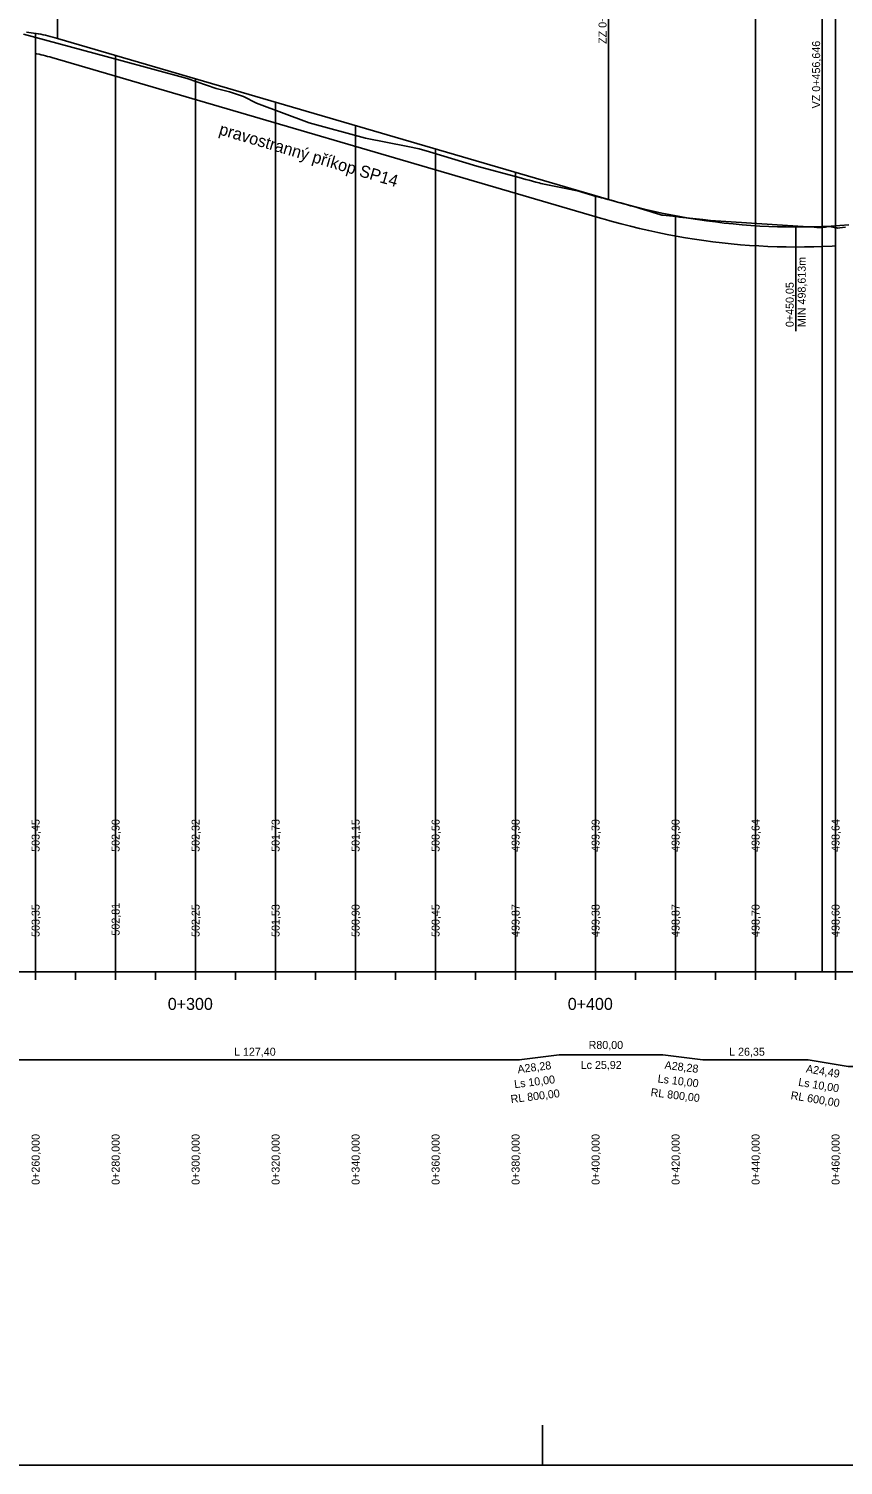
# Model space of a CAD drawing. Extents: x -632716 to -629545, y -1094726 to -1088285.
# Drawn here: x -632193.7 to -631990, y -1090378.9 to -1090019.9 of the extents above; entities that cross this region are included whole.
import ezdxf

# ---------------------------------------------------------------- set-up
doc = ezdxf.new("R2010")
doc.units = 0
for name, color, linetype in [('20', 7, 'Continuous'), ('Default', 7, 'Continuous'), ('formát', 7, 'Continuous'), ('NIVELETA_VYSKY', 7, 'Continuous'), ('PŘÍKOP', 7, 'Continuous'), ('REZ_POPIS', 7, 'Continuous'), ('REZ_TABULKA', 7, 'Continuous'), ('REZ_TENKA', 7, 'Continuous'), ('REZ_TLUSTA', 7, 'Continuous'), ('SKLONY_NIVELETA', 7, 'Continuous'), ('SKLONY_POPIS', 7, 'Continuous'), ('TECNY_NIVELETA', 7, 'Continuous'), ('TEREN_VYSKY', 7, 'Continuous'), ('VOZOVKA', 7, 'Continuous')]:
    doc.layers.add(name, color=color, linetype=linetype)

msp = doc.modelspace()

# ---------------------------------------------------------------- linework, layer by layer
at = {"layer": '20'}
for points in [[(-632191.95, -1090021.1), (-632191.95, -1090205.62), (-632191.95, -1090255.62), (-632191.95, -1090195.62)], [(-632171.95, -1090026.6), (-632171.95, -1090205.62), (-632171.95, -1090255.62), (-632171.95, -1090195.62)], [(-632151.95, -1090032.45), (-632151.95, -1090205.62), (-632151.95, -1090255.62), (-632151.95, -1090195.62)], [(-632131.95, -1090038.3), (-632131.95, -1090205.62), (-632131.95, -1090255.62), (-632131.95, -1090195.62)], [(-632111.95, -1090044.15), (-632111.95, -1090205.62), (-632111.95, -1090255.62), (-632111.95, -1090195.62)], [(-632091.95, -1090050), (-632091.95, -1090205.62), (-632091.95, -1090255.62), (-632091.95, -1090195.62)], [(-632071.95, -1090055.84), (-632071.95, -1090205.62), (-632071.95, -1090255.62), (-632071.95, -1090195.62)], [(-632051.95, -1090061.69), (-632051.95, -1090205.62), (-632051.95, -1090255.62), (-632051.95, -1090195.62)], [(-632031.95, -1090066.67), (-632031.95, -1090205.62), (-632031.95, -1090255.62), (-632031.95, -1090195.62)], [(-632011.95, -1090069.17), (-632011.95, -1090205.62), (-632011.95, -1090255.62), (-632011.95, -1090195.62)], [(-631991.95, -1090069.18), (-631991.95, -1090205.62), (-631991.95, -1090255.62), (-631991.95, -1090195.62)]]:
    msp.add_lwpolyline(points, dxfattribs=at)
at = {"layer": 'Default'}
msp.add_line((-632186.49, -1090022.35), (-632048.71, -1090062.64), dxfattribs=at)
for points in [[(-632194.25, -1090020.78), (-632193.65, -1090020.85), (-632193.06, -1090020.93), (-632192.46, -1090021.02), (-632191.86, -1090021.11), (-632191.27, -1090021.22), (-632190.67, -1090021.33), (-632190.07, -1090021.45), (-632189.48, -1090021.58), (-632188.88, -1090021.72), (-632188.28, -1090021.86), (-632187.68, -1090022.01), (-632187.09, -1090022.18), (-632186.49, -1090022.35)], [(-632048.71, -1090062.64), (-632046.48, -1090063.28), (-632044.26, -1090063.88), (-632042.03, -1090064.46), (-632039.81, -1090065), (-632037.58, -1090065.51), (-632035.36, -1090065.99), (-632033.13, -1090066.44), (-632030.91, -1090066.86), (-632028.68, -1090067.25), (-632026.46, -1090067.6), (-632024.23, -1090067.93), (-632022.01, -1090068.22), (-632019.78, -1090068.49), (-632017.56, -1090068.72), (-632015.33, -1090068.92), (-632013.11, -1090069.1), (-632010.88, -1090069.24), (-632008.66, -1090069.34), (-632006.43, -1090069.42), (-632004.21, -1090069.47), (-632001.98, -1090069.49), (-631999.76, -1090069.47), (-631997.53, -1090069.43), (-631993.08, -1090069.24), (-631990.86, -1090069.11), (-631988.63, -1090068.94)]]:
    msp.add_lwpolyline(points, dxfattribs=at)
at = {"layer": 'formát'}
msp.add_line((-632065.24, -1090378.9), (-632065.24, -1090368.9), dxfattribs=at)
msp.add_lwpolyline([(-632546.83, -1090378.9), (-629545.24, -1090378.9), (-629545.24, -1089784.9), (-632546.83, -1089784.9)], close=True, dxfattribs=at)
at = {"layer": 'PŘÍKOP'}
msp.add_line((-632187.89, -1090027.15), (-632050.11, -1090067.44), dxfattribs=at)
for points in [[(-632191.95, -1090026.18), (-632191.62, -1090026.24), (-632191.09, -1090026.34), (-632190.56, -1090026.46), (-632190.03, -1090026.58), (-632189.5, -1090026.71), (-632188.96, -1090026.85), (-632188.43, -1090026.99), (-632187.86, -1090027.15)], [(-632050.08, -1090067.45), (-632047.82, -1090068.1), (-632045.54, -1090068.72), (-632043.25, -1090069.31), (-632040.96, -1090069.86), (-632038.67, -1090070.39), (-632036.38, -1090070.89), (-632034.09, -1090071.35), (-632031.8, -1090071.78), (-632029.51, -1090072.18), (-632027.22, -1090072.55), (-632024.92, -1090072.88), (-632022.63, -1090073.19), (-632020.34, -1090073.46), (-632018.04, -1090073.7), (-632015.75, -1090073.91), (-632013.46, -1090074.08), (-632011.16, -1090074.23), (-632008.87, -1090074.34), (-632006.57, -1090074.42), (-632004.28, -1090074.47), (-632001.99, -1090074.49), (-631999.69, -1090074.47), (-631997.38, -1090074.43), (-631992.82, -1090074.24), (-631991.95, -1090074.18)]]:
    msp.add_lwpolyline(points, dxfattribs=at)
at = {"layer": 'REZ_TABULKA'}
msp.add_lwpolyline([(-632198.42, -1090277.62), (-632071.02, -1090277.62), (-632071.02, -1090277.62), (-632061.02, -1090276.37), (-632061.02, -1090276.37), (-632035.1, -1090276.37), (-632035.1, -1090276.37), (-632025.1, -1090277.62), (-632025.1, -1090277.62), (-631998.76, -1090277.62), (-631998.76, -1090277.62), (-631988.76, -1090279.29), (-631988.76, -1090279.29), (-631977.84, -1090279.29), (-631977.84, -1090279.29), (-631967.84, -1090277.62), (-631967.84, -1090277.62), (-631872.85, -1090277.62), (-631872.85, -1090277.22), (-631839.21, -1090277.22), (-631839.21, -1090277.62), (-631794.79, -1090277.62)], dxfattribs=at)
at = {"layer": 'REZ_TENKA'}
for p, q in [((-632191.95, -1090257.62), (-632191.95, -1090255.62)), ((-632181.95, -1090257.62), (-632181.95, -1090255.62)), ((-632171.95, -1090257.62), (-632171.95, -1090255.62)), ((-632161.95, -1090257.62), (-632161.95, -1090255.62)), ((-632141.95, -1090257.62), (-632141.95, -1090255.62)), ((-632131.95, -1090257.62), (-632131.95, -1090255.62)), ((-632121.95, -1090257.62), (-632121.95, -1090255.62)), ((-632111.95, -1090257.62), (-632111.95, -1090255.62)), ((-632101.95, -1090257.62), (-632101.95, -1090255.62)), ((-632091.95, -1090257.62), (-632091.95, -1090255.62)), ((-632081.95, -1090257.62), (-632081.95, -1090255.62)), ((-632071.95, -1090257.62), (-632071.95, -1090255.62)), ((-632061.95, -1090257.62), (-632061.95, -1090255.62)), ((-632041.95, -1090257.62), (-632041.95, -1090255.62)), ((-632031.95, -1090257.62), (-632031.95, -1090255.62)), ((-632021.95, -1090257.62), (-632021.95, -1090255.62)), ((-632011.95, -1090257.62), (-632011.95, -1090255.62)), ((-632001.95, -1090257.62), (-632001.95, -1090255.62)), ((-631991.95, -1090257.62), (-631991.95, -1090255.62))]:
    msp.add_line(p, q, dxfattribs=at)
at = {"layer": 'REZ_TLUSTA'}
for p, q in [((-632151.95, -1090257.62), (-632151.95, -1090253.62)), ((-632051.95, -1090257.62), (-632051.95, -1090253.62)), ((-632451.95, -1090255.62), (-629971.95, -1090255.62))]:
    msp.add_line(p, q, dxfattribs=at)
at = {"layer": 'SKLONY_NIVELETA'}
for p, q in [((-631995.31, -1089978.26), (-631995.31, -1090255.62)), ((-632186.49, -1090022.35), (-632048.71, -1090062.64))]:
    msp.add_line(p, q, dxfattribs=at)
for points in [[(-632194.25, -1090020.78), (-632193.65, -1090020.85), (-632193.06, -1090020.93), (-632192.46, -1090021.02), (-632191.86, -1090021.11), (-632191.27, -1090021.22), (-632190.67, -1090021.33), (-632190.07, -1090021.45), (-632189.48, -1090021.58), (-632188.88, -1090021.72), (-632188.28, -1090021.86), (-632187.68, -1090022.01), (-632187.09, -1090022.18), (-632186.49, -1090022.35)], [(-632048.71, -1090062.64), (-632046.48, -1090063.28), (-632044.26, -1090063.88), (-632042.03, -1090064.46), (-632039.81, -1090065), (-632037.58, -1090065.51), (-632035.36, -1090065.99), (-632033.13, -1090066.44), (-632030.91, -1090066.86), (-632028.68, -1090067.25), (-632026.46, -1090067.6), (-632024.23, -1090067.93), (-632022.01, -1090068.22), (-632019.78, -1090068.49), (-632017.56, -1090068.72), (-632015.33, -1090068.92), (-632013.11, -1090069.1), (-632010.88, -1090069.24), (-632008.66, -1090069.34), (-632006.43, -1090069.42), (-632004.21, -1090069.47), (-632001.98, -1090069.49), (-631999.76, -1090069.47), (-631997.53, -1090069.43), (-631993.08, -1090069.24), (-631990.86, -1090069.11), (-631988.63, -1090068.94)]]:
    msp.add_lwpolyline(points, dxfattribs=at)
at = {"layer": 'TECNY_NIVELETA'}
for p, q in [((-631991.95, -1090069.18), (-631991.95, -1089903.39)), ((-632011.95, -1090069.17), (-632011.95, -1089912.79)), ((-632186.49, -1090022.35), (-632186.49, -1089921.35)), ((-632048.71, -1090062.64), (-632048.71, -1089961.64)), ((-632001.91, -1090069.49), (-632001.91, -1090095.49))]:
    msp.add_line(p, q, dxfattribs=at)
at = {"layer": 'VOZOVKA'}
msp.add_lwpolyline([(-632195.01, -1090021.3), (-632171.26, -1090027.68), (-632154.09, -1090032.35), (-632146.79, -1090034.89), (-632143.45, -1090035.69), (-632140.01, -1090036.87), (-632136.72, -1090038.52), (-632123.56, -1090043.44), (-632109.49, -1090047.28), (-632098.92, -1090049.33), (-632096.05, -1090049.93), (-632093.44, -1090050.68), (-632081.66, -1090054.31), (-632071.02, -1090057.15), (-632070.19, -1090057.38), (-632069.35, -1090057.6), (-632068.52, -1090057.82), (-632067.69, -1090058.04), (-632066.85, -1090058.27), (-632066.02, -1090058.49), (-632065.65, -1090058.59), (-632065.19, -1090058.68), (-632064.35, -1090058.85), (-632063.52, -1090059.02), (-632062.69, -1090059.2), (-632061.85, -1090059.37), (-632061.02, -1090059.54), (-632060.21, -1090059.71), (-632059.4, -1090059.88), (-632058.59, -1090060.05), (-632057.78, -1090060.21), (-632056.97, -1090060.38), (-632056.16, -1090060.56), (-632055.66, -1090060.66), (-632055.35, -1090060.75), (-632054.54, -1090061), (-632053.73, -1090061.25), (-632052.92, -1090061.5), (-632052.11, -1090061.75), (-632052.11, -1090061.75), (-632051.3, -1090061.95), (-632050.49, -1090062.16), (-632049.68, -1090062.38), (-632048.87, -1090062.59), (-632048.06, -1090062.81), (-632047.25, -1090063.03), (-632046.44, -1090063.25), (-632045.63, -1090063.47), (-632044.82, -1090063.7), (-632044.01, -1090063.93), (-632043.2, -1090064.16), (-632042.39, -1090064.39), (-632041.58, -1090064.63), (-632040.77, -1090064.87), (-632039.96, -1090065.11), (-632039.15, -1090065.35), (-632038.34, -1090065.6), (-632037.53, -1090065.85), (-632036.72, -1090066.1), (-632035.91, -1090066.35), (-632035.4, -1090066.51), (-632035.1, -1090066.54), (-632034.27, -1090066.63), (-632033.44, -1090066.72), (-632032.6, -1090066.81), (-632031.77, -1090066.9), (-632030.94, -1090066.99), (-632030.1, -1090067.08), (-632029.27, -1090067.17), (-632028.44, -1090067.27), (-632027.6, -1090067.36), (-632026.77, -1090067.46), (-632025.94, -1090067.55), (-632025.1, -1090067.65), (-632023.21, -1090067.86), (-631998.76, -1090069.44), (-631998.04, -1090069.48), (-631997.33, -1090069.53), (-631996.61, -1090069.57), (-631995.9, -1090069.62), (-631995.25, -1090069.66), (-631995.19, -1090069.65), (-631994.47, -1090069.5), (-631993.76, -1090069.35), (-631993.67, -1090069.33), (-631993.04, -1090069.45), (-631992.33, -1090069.59), (-631991.61, -1090069.72), (-631991.46, -1090069.75), (-631990.9, -1090069.7), (-631990.19, -1090069.62), (-631989.47, -1090069.55)], dxfattribs=at)

# ---------------------------------------------------------------- texts
at = {"layer": 'NIVELETA_VYSKY'}
for s, p in [('503,45', (-632190.95, -1090225.62)), ('502,90', (-632170.95, -1090225.62)), ('502,32', (-632150.95, -1090225.62)), ('501,73', (-632130.95, -1090225.62)), ('501,15', (-632110.95, -1090225.62)), ('500,56', (-632090.95, -1090225.62)), ('499,98', (-632070.95, -1090225.62)), ('499,39', (-632050.95, -1090225.62)), ('498,90', (-632030.95, -1090225.62)), ('498,64', (-632010.95, -1090225.62)), ('498,64', (-631990.95, -1090225.62))]:
    msp.add_text(s, height=2, rotation=90, dxfattribs=at).set_placement(p)
at = {"layer": 'REZ_POPIS'}
for s, p in [('0+300', (-632158.91, -1090265.12)), ('0+400', (-632058.91, -1090265.12))]:
    msp.add_text(s, height=3, dxfattribs=at).set_placement(p)
at = {"layer": 'REZ_TABULKA'}
for s, p in [('L 127,40', (-632142.34, -1090276.56)), ('R80,00', (-632053.69, -1090274.87)), ('L 26,35', (-632018.56, -1090276.56)), ('Lc 25,92', (-632055.68, -1090279.87))]:
    msp.add_text(s, height=2, dxfattribs=at).set_placement(p)
for s, rotation, p in [('A28,28', 7.125, (-632071.35, -1090280.95)), ('A28,28', 352.875, (-632034.79, -1090279.81)), ('A24,49', 350.5377, (-631999.46, -1090280.72)), ('Ls 10,00', 7.125, (-632072.18, -1090284.68)), ('Ls 10,00', 352.875, (-632036.51, -1090283.22)), ('Ls 10,00', 350.5377, (-632001.37, -1090284.05)), ('RL 800,00', 7.125, (-632073.06, -1090288.42)), ('RL 800,00', 352.875, (-632038.28, -1090286.63)), ('RL 600,00', 350.5377, (-632003.28, -1090287.38)), ('0+260,000', 90, (-632190.95, -1090308.83)), ('0+280,000', 90, (-632170.95, -1090308.83)), ('0+300,000', 90, (-632150.95, -1090308.83)), ('0+320,000', 90, (-632130.95, -1090308.83)), ('0+340,000', 90, (-632110.95, -1090308.83)), ('0+360,000', 90, (-632090.95, -1090308.83)), ('0+380,000', 90, (-632070.95, -1090308.83)), ('0+400,000', 90, (-632050.95, -1090308.83)), ('0+420,000', 90, (-632030.95, -1090308.83)), ('0+440,000', 90, (-632010.95, -1090308.83)), ('0+460,000', 90, (-631990.95, -1090308.83))]:
    msp.add_text(s, height=2, rotation=rotation, dxfattribs=at).set_placement(p)
at = {"layer": 'SKLONY_POPIS'}
for s, height, rotation, p in [('ZZ 0+403,246', 2, 90, (-632049.21, -1090023.73)), ('VZ 0+456,646', 2, 90, (-631995.81, -1090039.84)), ('pravostranný příkop SP14', 3, 343.4322, (-632146.31, -1090046.31)), ('MIN 498,613m', 2, 90, (-631999.41, -1090094.49)), ('0+450,05', 2, 90, (-632002.41, -1090094.49))]:
    msp.add_text(s, height=height, rotation=rotation, dxfattribs=at).set_placement(p)
at = {"layer": 'TEREN_VYSKY'}
for s, p in [('503,35', (-632190.95, -1090246.88)), ('502,81', (-632170.95, -1090246.55)), ('502,25', (-632150.95, -1090246.88)), ('501,53', (-632130.95, -1090246.88)), ('500,90', (-632110.95, -1090246.88)), ('500,45', (-632090.95, -1090246.88)), ('499,87', (-632070.95, -1090246.88)), ('499,38', (-632050.95, -1090246.88)), ('498,87', (-632030.95, -1090246.88)), ('498,70', (-632010.95, -1090246.88)), ('498,60', (-631990.95, -1090246.88))]:
    msp.add_text(s, height=2, rotation=90, dxfattribs=at).set_placement(p)

doc.saveas('drawing.dxf')
